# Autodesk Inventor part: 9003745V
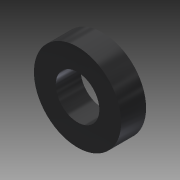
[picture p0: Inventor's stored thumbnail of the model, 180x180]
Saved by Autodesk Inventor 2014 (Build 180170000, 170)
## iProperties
Company: NHTSA/VRTC
Created: 2012-08
Material: Rubber
Document SubType Name: Modeling
Designer: Mike Vanvoorhis
Density: 0.93 g/cm^3
Mass: 5.79916 g
Surface Area: 28.0569 cm^2
Volume: 6.23566 cm^3
Description: WASHER, NEOPRENE RUBBER 5/8" SCREW SIZE, 1-5/16" OD, .375" THICK
Project: CHILD SIDE IMPACT SLED
Part Number: 9003745V
Appearance: Rubber - Black - Version 1.1
Author: Dave Walker
Title: Rubber Washer
Subject: Child Side Impact Sled
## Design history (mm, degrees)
sketch "Sketch1"
  geometry: C1 r 16.669 at (0, 0); C2 r 8.334 at (0, 0); 1 further point
  constraints: 2 centre point, 2 coincident
  dimensions: "d0" = 33.3375 diameter of C1; "d1" = 16.66875 diameter of C2
extrude "Extrusion1" new body sketch "Sketch1" distance "d2" = 9.525; taper "d3" = 0 deg
body "Solid1"
